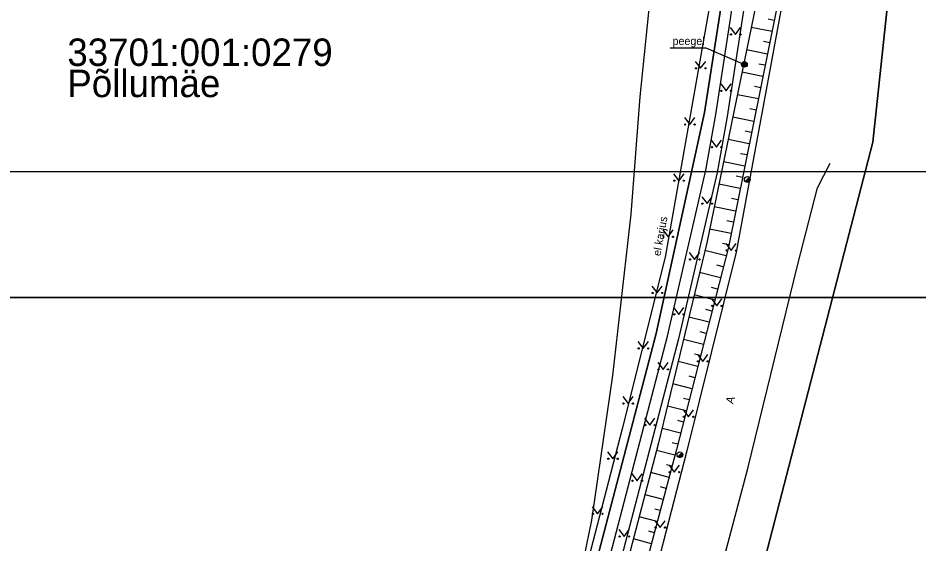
# Model space of a CAD drawing. Extents: x 554947 to 555436, y 6564938 to 6565792.
# Drawn here: x 555116.9 to 555195.6, y 6565202.4 to 6565248.3 of the extents above; entities that cross this region are included whole.
import ezdxf

# ---------------------------------------------------------------- set-up
doc = ezdxf.new("R2010")
doc.units = 0
for name, color, linetype in [('AED', 7, 'Continuous'), ('HALJASTUS', 7, 'Continuous'), ('KASUTUSALA', 7, 'Continuous'), ('KPKAABEL', 7, 'Continuous'), ('PIIR', 7, 'Continuous'), ('POST', 7, 'Continuous'), ('PR_SIDE', 7, 'Continuous'), ('RELJEEF', 7, 'Continuous'), ('TEE', 7, 'Continuous'), ('VORMISTUS', 7, 'Continuous')]:
    doc.layers.add(name, color=color, linetype=linetype)

msp = doc.modelspace()

# ---------------------------------------------------------------- linework, layer by layer
at = {"layer": 'AED'}
msp.add_lwpolyline([(555179.37, 6565300.078), (555180.242, 6565299.846), (555180.75, 6565290.874), (555180.137, 6565280.616), (555178.982, 6565264.788), (555177.984, 6565255.288), (555177.306, 6565249.05), (555173.486, 6565227.422), (555169.733, 6565212.423), (555163.779, 6565189.534), (555156.086, 6565161.758), (555151.428, 6565143.905), (555146.995, 6565125.891), (555142.273, 6565107.514), (555136.767, 6565086.759), (555131.214, 6565064.984), (555128.386, 6565056.617), (555127.142, 6565056.522)], dxfattribs=at)
at = {"layer": 'HALJASTUS'}
for p, q in [((555179.168, 6565247.514), (555179.632, 6565246.907)), ((555179.632, 6565246.907), (555180.077, 6565247.514)), ((555176.117, 6565244.548), (555176.58, 6565243.941)), ((555176.58, 6565243.941), (555177.026, 6565244.548)), ((555178.338, 6565242.583), (555178.802, 6565241.977)), ((555178.802, 6565241.977), (555179.247, 6565242.583)), ((555175.169, 6565239.638), (555175.632, 6565239.032)), ((555175.632, 6565239.032), (555176.078, 6565239.638)), ((555177.508, 6565237.653), (555177.971, 6565237.046)), ((555177.971, 6565237.046), (555178.417, 6565237.653)), ((555174.221, 6565234.729), (555174.684, 6565234.122)), ((555174.684, 6565234.122), (555175.13, 6565234.729)), ((555176.678, 6565232.722), (555177.141, 6565232.115)), ((555177.141, 6565232.115), (555177.587, 6565232.722)), ((555173.272, 6565229.82), (555173.736, 6565229.213)), ((555173.736, 6565229.213), (555174.181, 6565229.82)), ((555178.778, 6565228.624), (555179.241, 6565228.017)), ((555179.241, 6565228.017), (555179.687, 6565228.624)), ((555175.593, 6565227.849), (555176.057, 6565227.242)), ((555176.057, 6565227.242), (555176.502, 6565227.849)), ((555172.324, 6565224.911), (555172.788, 6565224.304)), ((555172.788, 6565224.304), (555173.233, 6565224.911)), ((555177.538, 6565223.78), (555178.001, 6565223.173)), ((555178.001, 6565223.173), (555178.447, 6565223.78)), ((555174.214, 6565223.043), (555174.677, 6565222.437)), ((555174.677, 6565222.437), (555175.123, 6565223.043)), ((555171.105, 6565220.065), (555171.568, 6565219.458)), ((555171.568, 6565219.458), (555172.014, 6565220.065)), ((555176.298, 6565218.936), (555176.762, 6565218.329)), ((555176.762, 6565218.329), (555177.207, 6565218.936)), ((555172.834, 6565218.237), (555173.298, 6565217.631)), ((555173.298, 6565217.631), (555173.743, 6565218.237)), ((555169.773, 6565215.246), (555170.236, 6565214.639)), ((555170.236, 6565214.639), (555170.682, 6565215.246)), ((555175.059, 6565214.092), (555175.522, 6565213.485)), ((555175.522, 6565213.485), (555175.968, 6565214.092)), ((555171.682, 6565213.373), (555172.146, 6565212.766)), ((555172.146, 6565212.766), (555172.591, 6565213.373)), ((555168.441, 6565210.426), (555168.904, 6565209.82)), ((555168.904, 6565209.82), (555169.35, 6565210.426)), ((555173.819, 6565209.248), (555174.282, 6565208.642)), ((555174.282, 6565208.642), (555174.728, 6565209.248)), ((555170.561, 6565208.5), (555171.024, 6565207.893)), ((555171.024, 6565207.893), (555171.47, 6565208.5)), ((555167.108, 6565205.607), (555167.572, 6565205)), ((555167.572, 6565205), (555168.017, 6565205.607)), ((555172.579, 6565204.404), (555173.043, 6565203.798)), ((555173.043, 6565203.798), (555173.488, 6565204.404)), ((555169.439, 6565203.627), (555169.903, 6565203.021)), ((555169.903, 6565203.021), (555170.348, 6565203.627))]:
    msp.add_line(p, q, dxfattribs=at)
for centre in [(555179.231, 6565246.907), (555180.059, 6565246.907), (555176.179, 6565243.941), (555177.008, 6565243.941), (555178.401, 6565241.977), (555179.229, 6565241.977), (555175.231, 6565239.032), (555176.06, 6565239.032), (555177.57, 6565237.046), (555178.399, 6565237.046), (555174.283, 6565234.122), (555175.112, 6565234.122), (555176.74, 6565232.115), (555177.569, 6565232.115), (555173.335, 6565229.213), (555174.164, 6565229.213), (555178.84, 6565228.017), (555179.669, 6565228.017), (555175.656, 6565227.242), (555176.485, 6565227.242), (555172.387, 6565224.304), (555173.216, 6565224.304), (555177.6, 6565223.173), (555178.429, 6565223.173), (555174.276, 6565222.437), (555175.105, 6565222.437), (555171.167, 6565219.458), (555171.996, 6565219.458), (555176.361, 6565218.329), (555177.189, 6565218.329), (555172.897, 6565217.631), (555173.725, 6565217.631), (555169.835, 6565214.639), (555170.664, 6565214.639), (555175.121, 6565213.485), (555175.95, 6565213.485), (555171.745, 6565212.766), (555172.574, 6565212.766), (555168.503, 6565209.82), (555169.332, 6565209.82), (555173.881, 6565208.642), (555174.71, 6565208.642), (555170.623, 6565207.893), (555171.452, 6565207.893), (555167.171, 6565205), (555168, 6565205), (555172.642, 6565203.798), (555173.471, 6565203.798), (555169.502, 6565203.021), (555170.33, 6565203.021)]:
    msp.add_circle(centre, 0.055, dxfattribs=at)
at = {"layer": 'KASUTUSALA'}
for points in [[(555181.453, 6565256.368), (555178.899, 6565239.742), (555178.02, 6565234.842), (555174.643, 6565220.286), (555166.41, 6565188.704), (555161.678, 6565171.117), (555158.189, 6565157.505), (555170.133, 6565154.484), (555169.631, 6565152.548), (555157.917, 6565155.511), (555157.535, 6565155.385), (555157.268, 6565155.019), (555157.089, 6565154.421), (555157.082, 6565153.274), (555146.55, 6565113.435), (555138.365, 6565081.692), (555129.025, 6565046.098)], [(555127.058, 6565046.777), (555141.002, 6565099.93), (555152.728, 6565144.628), (555155.084, 6565153.611), (555155.888, 6565156.675), (555156.912, 6565160.576), (555162.414, 6565181.549), (555172.651, 6565220.574), (555172.7, 6565220.76), (555176.927, 6565240.07), (555176.937, 6565240.135), (555179.22, 6565254.85)]]:
    msp.add_lwpolyline(points, dxfattribs=at)
at = {"layer": 'KPKAABEL'}
msp.add_lwpolyline([(555172.536, 6565254.014), (555171.281, 6565241.464), (555170.488, 6565231.192), (555168.866, 6565217.1), (555167.048, 6565204.461), (555164.351, 6565191.399), (555161.107, 6565179.306), (555157.628, 6565168.142), (555155.008, 6565156.873), (555154.465, 6565156.331), (555152.85, 6565155.986), (555149.5, 6565156.323)], dxfattribs=at)
at = {"layer": 'PIIR'}
msp.add_lwpolyline([(554962.55, 6565234.93), (555180.26, 6565306.43), (555180.8, 6565287.7), (555180.41, 6565269.99), (555179.22, 6565254.85), (555176.93, 6565240.09), (555172.7, 6565220.76), (555117.14, 6565008.97), (555108.27, 6564991.27)], close=True, dxfattribs=at)
for points in [[(555293.54, 6565286.23), (555256.63, 6565245.54), (555254.61, 6565228.5), (555255.75, 6565226.79), (555261.42, 6565218.27), (555289.11, 6565186.6), (555315.28, 6565149.09), (555315.73, 6565134.86), (555310.07, 6565124.47), (555303.59, 6565115.89), (555291.54, 6565100.48), (555288.85, 6565092.31), (555275.41, 6565088.83), (555273.15, 6565087.34), (555239.11, 6565139), (555231.12, 6565150.64), (555225.89, 6565157.13), (555173.21, 6565166.35), (555173.84, 6565168.77), (555191.64, 6565237.48), (555195.28, 6565271.63)], [(555195.28, 6565271.63), (555191.64, 6565237.48), (555173.84, 6565168.77), (555173.21, 6565166.35), (555172.58, 6565163.93), (555140.74, 6565041.04), (555133.32, 6565012.53), (555119.68, 6564972.95), (555107.79, 6564965.53), (555093.78, 6564958.98), (555080.97, 6564954.71), (555029.586, 6564944.201)], [(555029.586, 6564962.189), (555076.32, 6564971.61), (555087.28, 6564975.26), (555098.22, 6564980.37), (555106.03, 6564987.06), (555108.27, 6564991.27), (555117.14, 6565008.97), (555172.7, 6565220.76), (555176.93, 6565240.09), (555179.22, 6565254.85)]]:
    msp.add_lwpolyline(points, dxfattribs=at)
at = {"layer": 'POST'}
for p, q in [((555180.481, 6565234.051), (555180.835, 6565234.405)), ((555174.593, 6565209.995), (555174.947, 6565210.348))]:
    msp.add_line(p, q, dxfattribs=at)
msp.add_lwpolyline([(555173.91, 6565245.744), (555177.032, 6565245.744), (555180.409, 6565244.288)], dxfattribs=at)
for centre, radius in [((555180.409, 6565244.288), 0.25), ((555180.409, 6565244.288), 0.225), ((555180.409, 6565244.288), 0.2), ((555180.409, 6565244.288), 0.175), ((555180.409, 6565244.288), 0.15), ((555180.409, 6565244.288), 0.125), ((555180.409, 6565244.288), 0.1), ((555180.409, 6565244.288), 0.075), ((555180.409, 6565244.288), 0.05), ((555180.409, 6565244.288), 0.025), ((555180.659, 6565234.228), 0.25), ((555174.77, 6565210.171), 0.25)]:
    msp.add_circle(centre, radius, dxfattribs=at)
for centre, radius, start, end in [((555180.659, 6565234.228), 0.225, 224.85406, 45.03563), ((555180.659, 6565234.228), 0.2, 224.84272, 45.04698), ((555180.659, 6565234.228), 0.175, 224.82813, 45.06157), ((555180.659, 6565234.228), 0.15, 224.80867, 45.08103), ((555180.659, 6565234.228), 0.125, 224.78144, 45.10826), ((555180.659, 6565234.228), 0.1, 224.74058, 45.14911), ((555180.659, 6565234.228), 0.075, 224.67249, 45.2172), ((555180.659, 6565234.228), 0.05, 224.53632, 45.35338), ((555180.659, 6565234.228), 0.025, 224.12776, 45.76193), ((555174.77, 6565210.171), 0.225, 224.85406, 45.03563), ((555174.77, 6565210.171), 0.2, 224.84272, 45.04698), ((555174.77, 6565210.171), 0.175, 224.82813, 45.06157), ((555174.77, 6565210.171), 0.15, 224.80867, 45.08103), ((555174.77, 6565210.171), 0.125, 224.78144, 45.10826), ((555174.77, 6565210.171), 0.1, 224.74058, 45.14911), ((555174.77, 6565210.171), 0.075, 224.67249, 45.2172), ((555174.77, 6565210.171), 0.05, 224.53632, 45.35338), ((555174.77, 6565210.171), 0.025, 224.12776, 45.76193)]:
    msp.add_arc(centre, radius, start, end, dxfattribs=at)
at = {"layer": 'PR_SIDE'}
msp.add_lwpolyline([(555210.992, 6564988.671), (555132.015, 6564980.717), (555127.536, 6564982.26), (555122.65, 6564985.013), (555110.837, 6564991.67), (555110.653, 6564992.606), (555118.466, 6565008.131), (555128.057, 6565046.347), (555137.397, 6565081.944), (555145.583, 6565113.688), (555156.083, 6565153.408), (555156.093, 6565155.105), (555156.86, 6565156.343), (555160.711, 6565171.372), (555165.444, 6565188.961), (555173.672, 6565220.526), (555177.04, 6565235.044), (555177.913, 6565239.906), (555180.459, 6565256.479)], dxfattribs=at)
at = {"layer": 'RELJEEF'}
for p, q in [((555183.026, 6565248.126), (555182.481, 6565248.237)), ((555182.827, 6565247.146), (555181.007, 6565247.515)), ((555182.628, 6565246.166), (555182.081, 6565246.277)), ((555182.429, 6565245.186), (555180.602, 6565245.557)), ((555182.23, 6565244.206), (555181.681, 6565244.317)), ((555182.031, 6565243.226), (555180.198, 6565243.598)), ((555181.832, 6565242.246), (555181.281, 6565242.358)), ((555181.634, 6565241.266), (555179.793, 6565241.639)), ((555181.435, 6565240.286), (555180.882, 6565240.398)), ((555181.236, 6565239.306), (555179.388, 6565239.681)), ((555181.037, 6565238.326), (555180.482, 6565238.439)), ((555180.838, 6565237.346), (555178.984, 6565237.722)), ((555180.639, 6565236.366), (555180.082, 6565236.479)), ((555180.44, 6565235.386), (555178.579, 6565235.764)), ((555180.242, 6565234.406), (555179.682, 6565234.519)), ((555180.043, 6565233.426), (555178.174, 6565233.805)), ((555179.844, 6565232.446), (555179.282, 6565232.56)), ((555179.645, 6565231.466), (555177.77, 6565231.846)), ((555179.446, 6565230.486), (555178.882, 6565230.6)), ((555179.247, 6565229.506), (555177.365, 6565229.888)), ((555179.048, 6565228.526), (555178.483, 6565228.64)), ((555178.811, 6565227.554), (555176.958, 6565228.03)), ((555178.562, 6565226.586), (555178.011, 6565226.727)), ((555178.314, 6565225.617), (555176.49, 6565226.085)), ((555178.065, 6565224.649), (555177.522, 6565224.788)), ((555177.817, 6565223.68), (555176.021, 6565224.14)), ((555177.568, 6565222.711), (555177.034, 6565222.848)), ((555177.32, 6565221.743), (555175.553, 6565222.196)), ((555176.823, 6565219.805), (555175.085, 6565220.251)), ((555177.071, 6565220.774), (555176.546, 6565220.909)), ((555176.574, 6565218.837), (555176.057, 6565218.969)), ((555176.326, 6565217.868), (555174.616, 6565218.307)), ((555175.829, 6565215.931), (555174.148, 6565216.362)), ((555176.077, 6565216.899), (555175.569, 6565217.03)), ((555175.581, 6565214.962), (555175.08, 6565215.09)), ((555175.332, 6565213.994), (555173.679, 6565214.418)), ((555175.084, 6565213.025), (555174.592, 6565213.151)), ((555174.835, 6565212.056), (555173.211, 6565212.473)), ((555174.587, 6565211.088), (555174.104, 6565211.212)), ((555174.334, 6565210.12), (555172.733, 6565210.546)), ((555174.077, 6565209.154), (555173.597, 6565209.281)), ((555173.82, 6565208.187), (555172.226, 6565208.611)), ((555173.562, 6565207.221), (555173.085, 6565207.348)), ((555173.305, 6565206.255), (555171.719, 6565206.677)), ((555173.048, 6565205.288), (555172.573, 6565205.415)), ((555172.791, 6565204.322), (555171.212, 6565204.742)), ((555172.534, 6565203.355), (555172.061, 6565203.481)), ((555172.277, 6565202.389), (555170.705, 6565202.807))]:
    msp.add_line(p, q, dxfattribs=at)
for points in [[(555184.566, 6565294.895), (555185.953, 6565280.072), (555185.143, 6565263.746), (555184.046, 6565254.819), (555183.226, 6565249.112), (555179.005, 6565228.311), (555174.467, 6565210.622), (555168.444, 6565187.982), (555160.102, 6565161.063), (555157.57, 6565157.837)], [(555184.566, 6565294.895), (555182.784, 6565279.965), (555183.347, 6565264.524), (555181.678, 6565255.565), (555181.412, 6565249.474), (555177.118, 6565228.691), (555172.906, 6565211.208), (555166.985, 6565188.606), (555158.553, 6565161.251), (555157.57, 6565157.837)]]:
    msp.add_lwpolyline(points, dxfattribs=at)
at = {"layer": 'TEE'}
for points in [[(555183.594, 6565248.995), (555179.697, 6565227.862), (555175.388, 6565210.507), (555169.433, 6565187.479), (555162.32, 6565160.507), (555157.772, 6565142.96), (555152.674, 6565123.751), (555148.003, 6565106.069), (555142.307, 6565084.705), (555136.784, 6565063.937), (555131.82, 6565044.704), (555126.529, 6565024.437), (555123.003, 6565010.821), (555119.083, 6564999.093), (555116.16, 6564993.195), (555108.256, 6564982.259)], [(555114.997, 6564980.207), (555119.473, 6564986.791), (555121.429, 6564990.442), (555124.132, 6564996.667), (555128.448, 6565009.121), (555131.982, 6565022.769), (555137.234, 6565043.213), (555142.087, 6565062.036), (555147.465, 6565082.979), (555153.125, 6565104.459), (555157.981, 6565122.311), (555163.2, 6565141.618), (555168.3, 6565162.209), (555168.744, 6565163.563), (555174.483, 6565185.521), (555180.709, 6565208.971), (555185.087, 6565226.838), (555186.799, 6565233.51), (555187.911, 6565235.651)]]:
    msp.add_lwpolyline(points, dxfattribs=at)
at = {"layer": 'VORMISTUS'}
for points in [[(555029.586, 6565234.913), (555239.586, 6565234.913), (555239.586, 6564937.913), (555029.586, 6564937.913)], [(555039.586, 6564948.913), (555229.586, 6564948.913), (555229.586, 6565223.913), (555039.586, 6565223.913)], [(555039.586, 6565223.913), (555229.586, 6565223.913), (555229.586, 6564948.913), (555039.586, 6564948.913)]]:
    msp.add_lwpolyline(points, close=True, dxfattribs=at)

# ---------------------------------------------------------------- texts
at = {"layer": 'AED'}
msp.add_text('el karjus', height=0.7, rotation=79.8196, dxfattribs=at).set_placement((555173.072, 6565227.497))
at = {"layer": 'PIIR'}
for s, p in [('33701:001:0279', (555121.212, 6565244.147)), ('Põllumäe', (555121.212, 6565241.424))]:
    msp.add_text(s, height=2.4, dxfattribs=at).set_placement(p)
at = {"layer": 'POST'}
msp.add_text('peegel', height=0.7, rotation=359.95437, dxfattribs=at).set_placement((555174.124, 6565245.984))
at = {"layer": 'TEE'}
msp.add_text('A', height=0.7, rotation=73.10591, dxfattribs=at).set_placement((555179.419, 6565214.561))

doc.saveas('drawing.dxf')
